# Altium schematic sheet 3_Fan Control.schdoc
size 309 x 223 mm; Symbol: Sheet-Symbol_A4; Device: Sheet-Symbol_A4; Company: EasyEDA.com; Drawed: EasyEDA Pro; Reviewed: EasyEDA Pro; Version: V0.1; Page Size: A4; @Project Name: CM4-Nvme-NAS-main; @Page Count: 6; @Update Date: 2023-05-04; @Create Date: 2023-04-27; @Schematic Name: RaspberryPiNVMeNAS; Part Number: JLCPCB-002; @Page No: 1; @Page Name: Fan Control
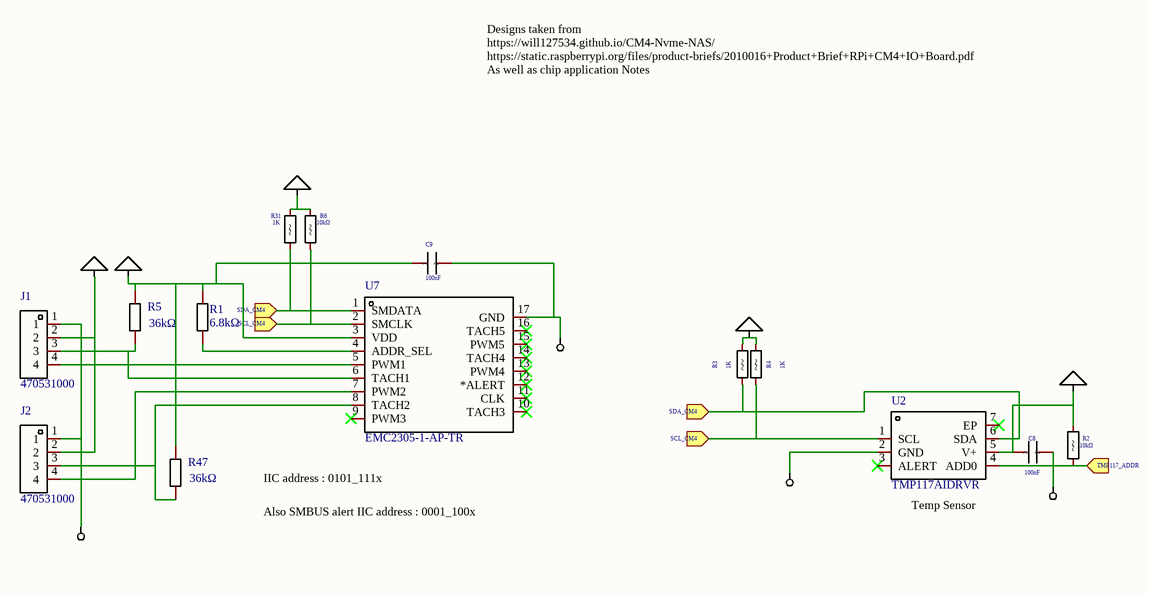
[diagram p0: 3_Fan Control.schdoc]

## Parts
C8  100nF  [C0402]
C9  100nF  [C0402]
J1  470531000  [CONN-TH_47053-1000]
J2  470531000  [CONN-TH_47053-1000]
R1  6.8kΩ  [R0402]
R2  10kΩ  [R0402]
R3  value 1K  [Resistor_SMD:R_0402_1005Metric]  (hidden comment: Device_R)
R4  value 1K  [Resistor_SMD:R_0402_1005Metric]  (hidden comment: Device_R)
R5  36kΩ  [R0402]
R6  10kΩ  [R0402]
R31  value 1K  [Resistor_SMD:R_0402_1005Metric]  (hidden comment: Device_R)
R47  36kΩ  [R0402]
U2  TMP117AIDRVR  [WDFN-6_L2.0-W2.0-P0.65-TL-EP]
U7  EMC2305-1-AP-TR  [QFN-16_L4.0-W4.0-P0.65-BL-EP2.2]

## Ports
SCL_CM4 (in), SDA_CM4 (in), TMP117_ADDR (in)

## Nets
POWER_+3.3V: C8.2 C9.1 R1.2 R2.2 R3.2 R4.2 R5.2 R6.2 R31.2 R47.2 U2.5(V+) U7.3(VDD)
POWER_+5V: J1.2 J2.2
POWER_GND: C8.1 C9.2 J1.1 J2.1 U2.2(GND) U7.17(GND)
SCL_CM4: R4.1 R6.1 U2.1(SCL) U7.2(SMCLK) ; port SCL_CM4
SDA_CM4: R3.1 R31.1 U2.6(SDA) U7.1(SMDATA) ; port SDA_CM4
TMP117_ADDR: R2.1 U2.4(ADD0) ; port TMP117_ADDR
NetJ1_3: J1.3 R5.1 U7.6(TACH1)
NetJ1_4: J1.4 U7.5(PWM1)
NetJ2_3: J2.3 R47.1 U7.8(TACH2)
NetJ2_4: J2.4 U7.7(PWM2)
NetR1_1: R1.1 U7.4(ADDR_SEL)

Not connected (* = marked no-connect by the designer): U2 3(ALERT)* 7(EP)*; U7 9(PWM3)* 10(TACH3)* 11(CLK)* 12(*ALERT)* 13(PWM4)* 14(TACH4)* 15(PWM5)* 16(TACH5)*

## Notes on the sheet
- Designs taken from
  https://will127534.github.io/CM4-Nvme-NAS/
  https://static.raspberrypi.org/files/product-briefs/2010016+Product+Brief+RPi+CM4+IO+Board.pdf
  As well as chip application Notes
- IIC address : 0101_111x
- Also SMBUS alert IIC address : 0001_100x
- (near U2) Temp Sensor

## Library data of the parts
C8 C9 = CL05B104KO5NNNC: Capacitance: Tolerance:±10% Tolerance:±10% Voltage Rated: Temperature Coefficient:; Manufacturer: SAMSUNG(三星); Add into BOM: yes; Tolerance: ±10%; Origin Footprint: C_0402_1005Metric
J1 J2 = 470531000: Reference Series:- Pitch:2.54mm Pins Structure:1x4P Number of Rows:1 Number of PINs Per Row:4 Row Spacing:- Gender:公型插针 Mounting Style:Straight Current Rating (Max):- Operating Temperature Range:- Operating Temperature Range:-; Manufacturer: MOLEX; Symbol: 47053-1000; Add into BOM: yes; Pitch: 2.54mm; Pins Structure: 1x4P; Number of PINs Per Row: 4; Gender: 公型插针
R1 R47 = 0402WGJ0103TCE: Type:Thick Film Resistors Resistance: Tolerance:±5% Tolerance:±5% Power(Watts): Temperature Coefficient:±100ppm/℃ Temperature Coefficient:±100ppm/℃ Overload Voltage (Max): Operating Temperature Range:-55℃~+155℃ Operating Temperature Range:-55℃~+155℃; Manufacturer: UNI-ROYAL(厚声); Add into BOM: yes; Tolerance: ±5%
R2 R6 = 0402WGF1002TCE: Type:Thick Film Resistors Resistance: Tolerance:±1% Tolerance:±1% Power(Watts): Temperature Coefficient:±100ppm/℃ Temperature Coefficient:±100ppm/℃ Overload Voltage (Max): Operating Temperature Range:-55℃~+155℃ Operating Temperature Range:-55℃~+155℃; Manufacturer: UNI-ROYAL(厚声); Add into BOM: yes; Tolerance: ±1%; Origin Footprint: R_0402_1005Metric
R3 R4 R31 = Device_R: Add into BOM: yes; Origin Footprint: R_0402_1005Metric
R5 = RC0402FR-0736KL: Type:Thick Film Resistors Resistance: Tolerance:±1% Tolerance:±1% Power(Watts): Temperature Coefficient:±100ppm/℃ Temperature Coefficient:±100ppm/℃ Overload Voltage (Max): Operating Temperature Range:-55℃~+155℃ Operating Temperature Range:-55℃~+155℃; Manufacturer: YAGEO(国巨); Add into BOM: yes; Tolerance: ±1%
U2 = TMP117AIDRVR: Manufacturer: TI(德州仪器); Add into BOM: yes
U7 = EMC2305-1-AP-TR: Type:- Supply Voltage:3V~3.6V Supply Voltage:3V~3.6V Output Current:- Interface:PWM Operating Temperature:-40℃~+125℃ Operating Temperature:-40℃~+125℃; Manufacturer: MICROCHIP(美国微芯); Add into BOM: yes; Interface: PWM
